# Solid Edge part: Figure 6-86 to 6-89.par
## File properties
Author: CADCIM
Template: Normal.par
Last saved by: Ashutosh-CADCIM
Revision: 8
Application: Solid Edge
Accuracy: 0.99
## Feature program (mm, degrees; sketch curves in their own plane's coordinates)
sketch for "unnamed Protrusion 1" plane through (0, 0, 0) normal (0, -1, 0) x-axis (1, 0, 0)
  arc centre (0, 0) radius 41.8395 from (-41.8395, 0) to (41.8395, 0) cw
  line (33.5782, 0) -> (41.8395, 0)
  arc centre (0, 0) radius 33.5782 from (-33.5782, 0) to (33.5782, 0) cw
  line (-41.8395, 0) -> (-33.5782, 0)
extrude "unnamed Protrusion 1" add finite 55 symmetric
sketch for "ExtrudedProtrusion_6" plane through (0, 0, 0) normal (0, -1, 0) x-axis (1, 0, 0)
  line (41.8395, 0) -> (76.8395, 0)
  line (76.8395, 0) -> (76.8395, 8.3056)
  line (76.8395, 8.3056) -> (41.0068, 8.3056)
extrude "ExtrudedProtrusion_6" add finite 35 symmetric
fillet "Round_2" radius 17.5
fillet "Round_3" radius 10
sketch for "Hole_2" plane through (58.6295, 0.0111, 8.3056) normal (0, 0, 1) x-axis (0, 1, 0)
  hole centre (-0.0111, -0.71) bore radius 5
hole "Hole_2" diameter 10 through  CounterBoreDepth = 2 mm
mirror "unnamed Mirror 1" of "ExtrudedProtrusion_6", "Round_2", "Round_3", "Hole_2" about plane through (0, 0, 0) normal (1, 0, 0)
extrude "unnamed Protrusion 2" add finite 35 symmetric
fillet "unnamed Round 1"
fillet "unnamed Round 2"
hole "unnamed Hole 1" through
body pattern "unnamed BodyPattern 1"
pattern "unnamed Pattern 1"
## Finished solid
Body 1: solid body, 40 faces, 88 edges, 46 vertices.
  Faces by surface: plane 20, cylinder 14, torus 6
  Edges by curve: circle 46, line 34, intersection 8
Bounding box of the edges (mm; curved faces can reach further): 153.679 x 110.000 x 41.840, from (-76.8395, -82.5, 0) to (76.8395, 27.5, 41.8395).
Cylindrical faces by radius (mm): R5 x4, R8 x4, R17.5 x4, R33.5782 x1, R41.8395 x1
Toroidal faces (ring radius, tube radius in mm): R51.8395 r10 x6
Planar faces by outward normal: +y 5, +z 8, -y 5, -z 2
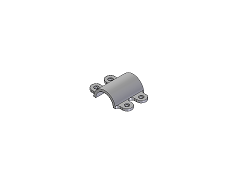
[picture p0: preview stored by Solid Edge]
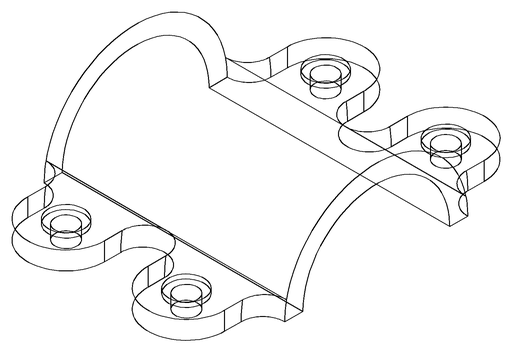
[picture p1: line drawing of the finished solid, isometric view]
